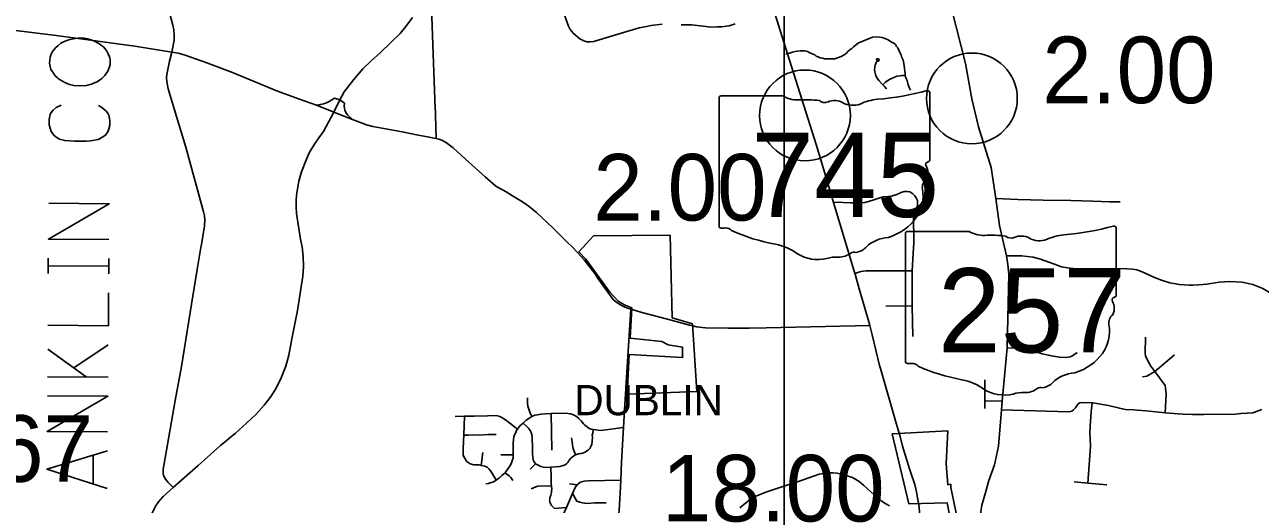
# Model space of a CAD drawing. Extents: x 1659811 to 1934326, y 644115 to 934867.
# Drawn here: x 1781767 to 1802180, y 769000 to 776927 of the extents above; entities that cross this region are included whole.
import ezdxf

# ---------------------------------------------------------------- set-up
doc = ezdxf.new("R2010")
doc.units = 0
for name, color, linetype in [('Default', 7, 'Continuous'), ('GM_X_Adjacent_County_Text', 7, 'Continuous'), ('GM_X_City_Street', 7, 'Continuous'), ('GM_X_Corporation', 7, 'Continuous'), ('GM_X_Corporation_Text', 7, 'Continuous'), ('GM_X_County_Road', 7, 'Continuous'), ('GM_X_State_Route', 7, 'Continuous'), ('GM_X_State_Shield', 7, 'Continuous'), ('SC_Scratch1', 7, 'Continuous')]:
    doc.layers.add(name, color=color, linetype=linetype)

msp = doc.modelspace()

# ---------------------------------------------------------------- linework, layer by layer
at = {"layer": 'Default'}
for centre in [(1797415, 775709), (1794657, 775427)]:
    msp.add_circle(centre, 750, dxfattribs=at)
at = {"layer": 'GM_X_Adjacent_County_Text'}
for p, q in [((1782155, 772817), (1782156, 773069)), ((1783155, 772811), (1783156, 773062)), ((1783155, 772937), (1782156, 772943)), ((1782577, 771255), (1783147, 771637)), ((1782146, 771566), (1782781, 771105)), ((1782143, 771109), (1783143, 771102)), ((1782898, 769805), (1782895, 769340))]:
    msp.add_line(p, q, dxfattribs=at)
for points in [[(1782186, 776234), (1782194, 776210), (1782201, 776187), (1782225, 776147), (1782240, 776124), (1782271, 776084), (1782303, 776052), (1782318, 776036), (1782350, 776013), (1782428, 775973), (1782507, 775941), (1782577, 775924), (1782680, 775916), (1782790, 775923), (1782869, 775946), (1782932, 775969), (1782964, 775985), (1783003, 776008), (1783043, 776039), (1783066, 776063), (1783090, 776086), (1783114, 776118), (1783138, 776157), (1783170, 776228), (1783178, 776267), (1783179, 776346), (1783171, 776377), (1783163, 776409), (1783148, 776448), (1783125, 776488), (1783109, 776511), (1783093, 776535), (1783070, 776559), (1783038, 776583), (1783015, 776599), (1782991, 776614), (1782968, 776630), (1782921, 776654), (1782866, 776678), (1782803, 776694), (1782748, 776703), (1782740, 776703), (1782685, 776703), (1782638, 776704), (1782575, 776696), (1782512, 776681), (1782464, 776665), (1782409, 776642), (1782362, 776619), (1782314, 776580), (1782282, 776548), (1782251, 776517), (1782227, 776486), (1782203, 776439), (1782187, 776392), (1782179, 776344), (1782178, 776289), (1782186, 776234)], [(1782370, 775595), (1782284, 775556), (1782236, 775517), (1782204, 775478), (1782188, 775447), (1782172, 775360), (1782171, 775274), (1782202, 775163), (1782249, 775100), (1782288, 775068), (1782343, 775036), (1782429, 775012), (1782587, 775003), (1782705, 775002), (1782784, 775002), (1782855, 775009), (1782981, 775032), (1783004, 775040), (1783060, 775071), (1783099, 775102), (1783139, 775157), (1783155, 775204), (1783171, 775267), (1783172, 775338), (1783164, 775409), (1783157, 775432), (1783141, 775464), (1783110, 775496), (1783071, 775535), (1783024, 775567), (1782985, 775591)], [(1783158, 773377), (1782158, 773384), (1783162, 773968), (1782163, 773975)], [(1782149, 771959), (1783149, 771952), (1783152, 772496)], [(1783137, 770197), (1782137, 770204), (1783141, 770787), (1782141, 770794)], [(1783131, 769260), (1782133, 769582), (1783135, 769882)]]:
    msp.add_lwpolyline(points, dxfattribs=at)
at = {"layer": 'GM_X_City_Street'}
for points in [[(1784685, 773296), (1784735, 773603), (1784745, 773698), (1784736, 773770), (1784721, 773835), (1784428, 774903), (1784235, 775534), (1784138, 775865), (1784125, 775929), (1784115, 775990), (1784111, 776055), (1784114, 776105), (1784158, 776324), (1784196, 776473), (1784235, 776672), (1784238, 776744), (1784231, 776844), (1784215, 776918), (1784131, 777234), (1783629, 779189), (1783538, 779530), (1783263, 780534), (1783093, 781151)], [(1788551, 775488), (1788549, 775542), (1788539, 775845), (1788512, 776595), (1788492, 777063), (1788470, 777429)], [(1790658, 777159), (1790751, 776900), (1790777, 776845), (1790832, 776780), (1790937, 776695), (1791003, 776661), (1791054, 776642), (1791106, 776642), (1791170, 776649), (1791259, 776676), (1791606, 776781), (1791919, 776873), (1792011, 776891), (1792118, 776916), (1792297, 776934)], [(1786330, 773355), (1786325, 773382), (1786259, 773807), (1786250, 773917), (1786254, 774036), (1786263, 774150), (1786294, 774341), (1786338, 774493), (1786420, 774704), (1786472, 774820), (1786567, 774969), (1786624, 775055), (1786702, 775162), (1786871, 775480), (1786971, 775687), (1787044, 775818), (1787200, 776018), (1787355, 776199), (1787487, 776323), (1787646, 776467), (1787967, 776780), (1788061, 776896), (1788172, 777044)], [(1792613, 776927), (1792783, 776923), (1792974, 776902), (1793100, 776887), (1793202, 776892), (1793276, 776890), (1793407, 776911), (1793502, 776942)], [(1781034, 776910), (1781525, 776843), (1782284, 776747), (1783301, 776608), (1783588, 776571), (1784196, 776473)], [(1794341, 776439), (1794370, 776448), (1794451, 776472), (1794498, 776483), (1794535, 776490), (1794578, 776494), (1794616, 776497), (1794651, 776494), (1794683, 776488), (1794712, 776477), (1794740, 776463), (1794779, 776444), (1794818, 776427), (1794842, 776409), (1794875, 776396), (1794909, 776382), (1794948, 776373), (1794981, 776365), (1795025, 776364), (1795058, 776361), (1795107, 776362), (1795149, 776364), (1795195, 776381), (1795228, 776391), (1795269, 776409), (1795306, 776427), (1795338, 776453), (1795366, 776482), (1795402, 776515), (1795430, 776533), (1795459, 776561), (1795507, 776597), (1795544, 776625), (1795575, 776640), (1795624, 776663), (1795670, 776678), (1795709, 776696), (1795771, 776719), (1795838, 776725), (1795886, 776722), (1795932, 776715), (1795976, 776701), (1796020, 776682), (1796065, 776656), (1796088, 776641), (1796124, 776622), (1796153, 776597), (1796171, 776568), (1796189, 776543), (1796207, 776505), (1796226, 776467), (1796246, 776429), (1796259, 776383), (1796277, 776343), (1796290, 776286), (1796298, 776247), (1796302, 776203), (1796308, 776160), (1796313, 776123), (1796311, 776089), (1796321, 776063), (1796331, 776039), (1796345, 776004), (1796365, 775935), (1796386, 775876), (1796399, 775845)], [(1784196, 776473), (1784304, 776457), (1784415, 776425), (1784775, 776295), (1785202, 776135), (1785945, 775831), (1786304, 775696), (1786590, 775596), (1786871, 775480), (1787181, 775362), (1787342, 775300), (1787411, 775274), (1787519, 775244), (1788001, 775154), (1788269, 775099), (1788392, 775079), (1788532, 775051)], [(1796007, 775869), (1795972, 775907), (1795944, 775934), (1795878, 776005), (1795852, 776042), (1795833, 776072), (1795820, 776102), (1795810, 776150), (1795805, 776187), (1795810, 776221), (1795817, 776259), (1795829, 776286), (1795840, 776313), (1795845, 776321), (1795860, 776324), (1795874, 776331), (1795882, 776338), (1795881, 776352), (1795879, 776360), (1795874, 776365), (1795868, 776368), (1795860, 776365), (1795852, 776365), (1795841, 776361), (1795838, 776356), (1795839, 776349), (1795842, 776339), (1795853, 776323)], [(1795944, 775934), (1795987, 775978), (1796044, 776015), (1796087, 776039), (1796128, 776052), (1796177, 776075), (1796228, 776084), (1796263, 776090), (1796311, 776089)], [(1786971, 775687), (1786883, 775714), (1786799, 775658), (1786752, 775635), (1786705, 775620), (1786653, 775610), (1786590, 775596)], [(1787181, 775362), (1787102, 775437), (1787074, 775478), (1787058, 775514), (1787047, 775581), (1787050, 775630), (1786971, 775687)], [(1788553, 775432), (1788551, 775488)], [(1788566, 775044), (1788553, 775432)], [(1788532, 775051), (1788566, 775044), (1788608, 775035), (1788660, 775017), (1788735, 774973), (1788780, 774943), (1788844, 774889), (1789044, 774708), (1789373, 774412), (1789549, 774260), (1789720, 774163), (1789825, 774100), (1789963, 774014), (1790039, 773965), (1790129, 773902), (1790224, 773825), (1790392, 773663), (1790495, 773565), (1790720, 773346), (1790822, 773244), (1790886, 773175)], [(1795129, 773990), (1795213, 773994), (1795290, 773990), (1795410, 773985), (1795490, 773982), (1795586, 773981), (1795646, 773988), (1795705, 774002), (1795780, 774029), (1795893, 774068), (1795951, 774080), (1796030, 774087), (1796079, 774093), (1796122, 774103), (1796174, 774120), (1796247, 774154), (1796297, 774168), (1796341, 774172), (1796388, 774162), (1796433, 774139), (1796473, 774101), (1796497, 774065), (1796514, 774021), (1796519, 773985), (1796515, 773940), (1796499, 773878), (1796465, 773780), (1796453, 773723), (1796450, 773664), (1796449, 773613), (1796456, 773496), (1796458, 773320), (1796444, 773152)], [(1797809, 774055), (1798172, 774036), (1798594, 774027), (1799049, 774019), (1799413, 774009), (1799687, 773999), (1799865, 774001)], [(1784219, 769275), (1784630, 769643), (1785003, 769974), (1785250, 770175), (1785431, 770342), (1785586, 770486), (1785725, 770636), (1785822, 770764), (1785915, 770909), (1786003, 771088), (1786080, 771284), (1786130, 771467), (1786180, 771733), (1786271, 772205), (1786359, 772769), (1786375, 772928), (1786368, 773096), (1786350, 773256), (1786330, 773355)], [(1784617, 772879), (1784677, 773247), (1784685, 773296)], [(1790886, 773175), (1790898, 773162), (1791008, 773039), (1791186, 772817), (1791243, 772729), (1791399, 772507), (1791490, 772387), (1791532, 772349), (1791580, 772312), (1791646, 772274), (1791724, 772243), (1791780, 772223)], [(1796444, 773152), (1796429, 772857), (1796429, 772273), (1796440, 771773)], [(1797988, 773106), (1798240, 773106), (1798334, 773098), (1798427, 773084), (1798551, 773050), (1798780, 772969), (1798894, 772927), (1798995, 772906), (1799091, 772898), (1799975, 772889), (1800066, 772886), (1800142, 772874), (1800230, 772844), (1800351, 772786), (1800430, 772749), (1800549, 772702), (1800684, 772663), (1800785, 772644), (1800841, 772633), (1801003, 772622), (1801065, 772623)], [(1784213, 769281), (1784139, 769359), (1784090, 769415), (1784062, 769474), (1784054, 769512), (1784054, 769579), (1784065, 769640), (1784254, 770715), (1784357, 771275), (1784523, 772309), (1784617, 772879)], [(1795483, 772817), (1795583, 772849), (1795668, 772859), (1795914, 772857), (1796218, 772860), (1796429, 772857)], [(1801065, 772623), (1801163, 772625), (1801294, 772639), (1801500, 772672), (1801677, 772685), (1801881, 772671), (1802058, 772631), (1802221, 772564), (1802417, 772452), (1802750, 772181), (1802908, 772052), (1802992, 772000), (1803043, 771979), (1803126, 771960), (1803319, 771948)], [(1795994, 772279), (1796429, 772273)], [(1791581, 768845), (1791586, 768900), (1791605, 769182), (1791616, 769401), (1791627, 769698), (1791662, 770268), (1791678, 770556), (1791717, 771182), (1791780, 772223)], [(1792807, 771948), (1792863, 771935), (1792915, 771925), (1793012, 771917), (1793389, 771912), (1793735, 771912), (1794014, 771915), (1795728, 771954)], [(1800611, 770514), (1800625, 770825), (1800614, 770917), (1800606, 770963), (1800436, 771196), (1800371, 771285), (1800320, 771371), (1800283, 771452), (1800276, 771500), (1800285, 771760)], [(1797996, 771587), (1798304, 771573), (1798374, 771568), (1798439, 771537), (1798511, 771510), (1798578, 771485), (1798680, 771462), (1798758, 771449), (1798868, 771430), (1798959, 771427), (1799038, 771436), (1799068, 771447), (1799156, 771510)], [(1800436, 771196), (1800765, 771470)], [(1797627, 770584), (1797628, 770710), (1797629, 771055)], [(1800235, 771108), (1800307, 771117), (1800436, 771196)], [(1790146, 770451), (1790111, 770523), (1790088, 770586), (1790081, 770624), (1790076, 770674), (1790076, 770761)], [(1797628, 770710), (1797918, 770704)], [(1797905, 770559), (1799022, 770530), (1799064, 770538), (1799094, 770562), (1799126, 770593), (1799173, 770659), (1799200, 770678), (1799242, 770682), (1799403, 770676), (1799411, 770676), (1799673, 770632), (1799854, 770588), (1799974, 770563), (1800038, 770564), (1800143, 770554), (1800293, 770542), (1800611, 770514), (1800822, 770496), (1800908, 770489), (1801060, 770485), (1801244, 770484), (1801768, 770492), (1801856, 770499), (1802058, 770514), (1802207, 770567)], [(1799330, 769348), (1799372, 769953), (1799368, 770087), (1799365, 770184), (1799370, 770292), (1799387, 770528), (1799403, 770676)], [(1788880, 770451), (1789030, 770455), (1789035, 770455), (1789192, 770459), (1789410, 770464), (1789554, 770466), (1789598, 770457), (1789628, 770445), (1789679, 770416), (1789734, 770377), (1789910, 770244)], [(1789556, 769401), (1789496, 769501), (1789461, 769552), (1789433, 769586), (1789406, 769611), (1789367, 769632), (1789319, 769640), (1789308, 769642), (1789268, 769650), (1789186, 769654), (1789125, 769668), (1789093, 769692), (1789065, 769714), (1789044, 769749), (1789023, 769786), (1789012, 769816), (1789009, 769856), (1789010, 769914), (1789018, 770043), (1789022, 770141), (1789035, 770455)], [(1789387, 769340), (1789427, 769344), (1789472, 769360), (1789499, 769367), (1789538, 769389), (1789556, 769401), (1789562, 769405), (1789611, 769436), (1789650, 769473), (1789683, 769505), (1789698, 769520), (1789711, 769533), (1789739, 769567), (1789766, 769607), (1789786, 769639), (1789801, 769671), (1789817, 769702), (1789826, 769732), (1789838, 769763), (1789836, 769815), (1789834, 769869), (1789834, 769948), (1789839, 770012), (1789842, 770069), (1789849, 770113), (1789859, 770148), (1789873, 770176), (1789887, 770202), (1789899, 770228), (1789910, 770244), (1789949, 770295), (1790004, 770342), (1790054, 770391), (1790110, 770430), (1790146, 770451), (1790197, 770471), (1790236, 770480), (1790296, 770490), (1790364, 770497), (1790463, 770500), (1790703, 770505), (1790786, 770495), (1790834, 770479), (1790885, 770450), (1790923, 770416), (1790958, 770377), (1790997, 770329), (1791023, 770307), (1791059, 770279), (1791094, 770254), (1791126, 770244), (1791158, 770237), (1791284, 770221), (1791662, 770268)], [(1790477, 769893), (1790463, 770500)], [(1790208, 769671), (1790175, 769720), (1790167, 769742), (1790159, 769780), (1790154, 769833), (1790156, 769916), (1790153, 770120), (1790144, 770147), (1790133, 770188), (1790116, 770222), (1790089, 770259), (1790072, 770275), (1790004, 770342)], [(1790238, 769651), (1790269, 769637), (1790296, 769626), (1790335, 769614), (1790380, 769610), (1790459, 769614), (1790609, 769622), (1790648, 769635), (1790695, 769654), (1790716, 769667), (1790737, 769691), (1790753, 769711), (1790785, 769755), (1790809, 769778), (1790839, 769800), (1790866, 769818), (1790915, 769833), (1790958, 769842), (1790997, 769853), (1791027, 769861), (1791053, 769881), (1791079, 769900), (1791101, 769924), (1791120, 769957), (1791138, 769996), (1791143, 770042), (1791145, 770109), (1791144, 770143), (1791152, 770176), (1791158, 770237)], [(1789022, 770141), (1789097, 770144), (1789163, 770148), (1789279, 770145), (1789417, 770152), (1789557, 770152)], [(1790866, 769818), (1790831, 769903), (1790823, 769936), (1790815, 769984), (1790809, 770033), (1790802, 770099)], [(1789308, 769642), (1789333, 769854)], [(1789631, 769816), (1789836, 769815)], [(1790120, 769582), (1790208, 769671), (1790237, 769652), (1790238, 769651)], [(1790715, 768948), (1790521, 768932), (1790491, 768958), (1790470, 768979), (1790460, 769000), (1790446, 769026), (1790443, 769042), (1790439, 769063), (1790440, 769087), (1790443, 769109), (1790460, 769152), (1790470, 769195), (1790472, 769219), (1790478, 769255), (1790470, 769292), (1790469, 769305), (1790467, 769331), (1790465, 769451), (1790459, 769614)], [(1789698, 769520), (1789768, 769470), (1789798, 769442), (1789832, 769393)], [(1790553, 768589), (1790715, 768948), (1790816, 769180), (1790859, 769277), (1790893, 769321), (1790940, 769358), (1790968, 769370), (1791009, 769383), (1791080, 769388), (1791616, 769401)], [(1793579, 768939), (1793674, 769021), (1793754, 769080), (1793843, 769132), (1794027, 769208), (1794341, 769310), (1794532, 769373), (1794798, 769467), (1794892, 769496), (1795005, 769514), (1795068, 769519), (1795116, 769518), (1795189, 769512), (1795261, 769500), (1795334, 769477), (1795440, 769440), (1795497, 769407), (1795552, 769375), (1795628, 769311), (1795747, 769206), (1795844, 769120), (1795901, 769069), (1795996, 769010), (1796054, 768976)], [(1799105, 769369), (1799330, 769348), (1799645, 769319)], [(1783804, 768056), (1783780, 768394), (1783780, 768450), (1783783, 768525), (1783798, 768648), (1783813, 768714), (1783836, 768775), (1783866, 768846), (1783898, 768910), (1783928, 768970), (1783978, 769042), (1784055, 769126), (1784219, 769275), (1784213, 769281)], [(1790135, 769254), (1790209, 769289), (1790243, 769301), (1790469, 769305)], [(1790767, 769338), (1790893, 769321)], [(1790816, 769180), (1790890, 769050), (1790937, 769034), (1790980, 769025), (1791018, 769016), (1791067, 769014), (1791178, 769023), (1791375, 769026)]]:
    msp.add_lwpolyline(points, dxfattribs=at)
at = {"layer": 'GM_X_Corporation'}
msp.add_lwpolyline([(1791769, 771744), (1792292, 771693), (1792400, 771637), (1792636, 771596), (1792636, 771425), (1791754, 771473), (1791720, 770818), (1792869, 770863), (1792799, 771981), (1792464, 772084), (1792432, 773446), (1791163, 773438), (1790923, 773175), (1791037, 773050), (1791431, 772506), (1791571, 772357), (1791625, 772322), (1791688, 772291), (1791795, 772249)], close=True, dxfattribs=at)
msp.add_lwpolyline([(1791769, 771744), (1792292, 771693), (1792400, 771637), (1792636, 771596), (1792636, 771425), (1791754, 771473), (1791720, 770818), (1792869, 770863), (1792799, 771981), (1792464, 772084), (1792432, 773446), (1791163, 773438), (1790923, 773175), (1791037, 773050), (1791431, 772506), (1791571, 772357), (1791625, 772322), (1791688, 772291), (1791795, 772249)], close=True, dxfattribs=at)
msp.add_lwpolyline([(1797178, 768750), (1797069, 769278), (1797065, 769330), (1797015, 769322), (1796989, 769674), (1797017, 770212), (1796099, 770163), (1796374, 769005), (1797006, 769026), (1797045, 768825)], dxfattribs=at)
msp.add_lwpolyline([(1797178, 768750), (1797069, 769278), (1797065, 769330), (1797015, 769322), (1796989, 769674), (1797017, 770212), (1796099, 770163), (1796374, 769005), (1797006, 769026), (1797045, 768825)], dxfattribs=at)
at = {"layer": 'GM_X_County_Road'}
msp.add_lwpolyline([(1791780, 772223), (1791982, 772166), (1792387, 772058), (1792748, 771962), (1792807, 771948)], dxfattribs=at)
at = {"layer": 'GM_X_State_Route'}
for points in [[(1794934, 774636), (1794841, 774945), (1794370, 776448), (1793373, 779630)], [(1797529, 768657), (1797548, 768766), (1797581, 768985), (1797643, 769214), (1797690, 769377), (1797786, 769653), (1797853, 769962), (1797905, 770559), (1797918, 770704), (1797996, 771587), (1797996, 771591), (1798023, 772805), (1798010, 772961), (1797988, 773106), (1797874, 773609), (1797809, 774055), (1797734, 774564), (1797526, 775241), (1797415, 775699), (1797309, 776284), (1797086, 777175)], [(1795323, 773347), (1795129, 773990), (1794934, 774636)], [(1795488, 772801), (1795483, 772817), (1795323, 773347)], [(1795700, 772053), (1795555, 772562), (1795488, 772801)], [(1795765, 771801), (1795728, 771954), (1795700, 772053)], [(1795905, 771243), (1795890, 771296), (1795765, 771801)], [(1796165, 770339), (1795905, 771243)], [(1796384, 769586), (1796267, 769959), (1796228, 770123), (1796165, 770339)], [(1796513, 769134), (1796505, 769178), (1796470, 769325), (1796410, 769506), (1796384, 769586)], [(1796522, 769083), (1796519, 769102), (1796513, 769134)], [(1796549, 768771), (1796548, 768877), (1796544, 768948), (1796522, 769083)]]:
    msp.add_lwpolyline(points, dxfattribs=at)
at = {"layer": 'GM_X_State_Shield'}
for p, q in [((1793238, 775714), (1793238, 773601)), ((1794292, 775750), (1793273, 775750)), ((1796719, 774697), (1796719, 775803)), ((1796718, 774698), (1796719, 774697)), ((1796318, 773474), (1796318, 771361)), ((1797372, 773511), (1796353, 773511)), ((1799799, 772458), (1799799, 773563)), ((1799798, 772458), (1799799, 772458))]:
    msp.add_line(p, q, dxfattribs=at)
for centre, major_axis, start_param, end_param in [((1793278, 775719), (40.3, 0), 1.712693, 3.28349), ((1794535, 775996), (391, 0), 4.042523, 4.731795), ((1795479, 778632), (3691, 0), 4.814394, 5.042369), ((1796680, 775807), (38.7, 0), 6.141152, 7.989035), ((1794664, 774564), (1404, 0), 1.404758, 1.657858), ((1794983, 775730), (113, 0), 3.836095, 5.185415), ((1795149, 775485), (235, 0), 0.950623, 2.079405), ((1795451, 775820), (282, 0), 4.081561, 5.145723), ((1795950, 775105), (743, 0), 1.699011, 2.107814), ((1796677, 774693), (41.5, 0), 5.05454, 6.418171), ((1796710, 774616), (60, 0), 1.883978, 3.671073), ((1796328, 774476), (360, 0), 5.934695, 6.695948), ((1796858, 774235), (262, 0), 2.387724, 3.262537), ((1795686, 774094), (923, 0), 5.101752, 6.440018), ((1793279, 773596), (40.7, 0), 3.00124, 4.508301), ((1793285, 773812), (310, 0), 4.665946, 4.897461), ((1793348, 773479), (112, 0), 0.519207, 1.627899), ((1794761, 775378), (2665, 0), 4.195997, 4.488961), ((1796358, 773479), (40.3, 0), 1.712693, 3.28349), ((1797615, 773756), (391, 0), 4.042523, 4.731795), ((1797744, 772324), (1404, 0), 1.404758, 1.657858), ((1799030, 772865), (743, 0), 1.699011, 2.107814), ((1798559, 776392), (3691, 0), 4.814394, 5.042369), ((1799760, 773568), (38.7, 0), 6.141152, 7.989035), ((1793967, 772651), (834, 0), 0.823519, 1.323587), ((1795434, 773396), (298, 0), 4.937069, 5.64225), ((1796075, 773007), (506, 0), 1.647645, 2.488434), ((1798063, 773490), (113, 0), 3.836095, 5.185415), ((1798229, 773246), (235, 0), 0.950623, 2.079405), ((1798531, 773581), (282, 0), 4.081561, 5.145723), ((1794869, 773468), (529, 0), 4.026481, 4.996735), ((1795175, 772738), (435, 0), 1.495662, 1.94098), ((1795213, 773310), (282, 0), 4.691044, 5.507374), ((1795468, 773105), (79.4, 0), 1.147584, 2.315152), ((1799757, 772453), (41.5, 0), 5.05454, 6.418171), ((1799790, 772377), (60, 0), 1.883978, 3.671073), ((1799408, 772237), (360, 0), 5.934695, 6.695948), ((1799938, 771995), (262, 0), 2.387724, 3.262537), ((1798766, 771854), (923, 0), 5.101752, 6.440018), ((1796359, 771357), (40.7, 0), 3.00124, 4.508301), ((1796365, 771573), (310, 0), 4.665946, 4.897461), ((1796428, 771239), (112, 0), 0.519207, 1.627899), ((1797841, 773138), (2665, 0), 4.195997, 4.488961), ((1797047, 770412), (834, 0), 0.823519, 1.323587), ((1798514, 771156), (298, 0), 4.937069, 5.64225), ((1799155, 770768), (506, 0), 1.647645, 2.488434), ((1797949, 771229), (529, 0), 4.026481, 4.996735), ((1798255, 770498), (435, 0), 1.495662, 1.94098), ((1798293, 771071), (282, 0), 4.691044, 5.507374), ((1798548, 770866), (79.4, 0), 1.147584, 2.315152)]:
    msp.add_ellipse(centre, major_axis=major_axis, ratio=0.8, start_param=start_param, end_param=end_param, dxfattribs=at)
at = {"layer": 'SC_Scratch1'}
msp.add_lwpolyline([(1659811, 738617), (1659811, 934867), (1794311, 934867), (1794311, 738617)], close=True, dxfattribs=at)

# ---------------------------------------------------------------- texts
at = {"layer": 'Default'}
for s, p in [('2.00', (1798579, 775630)), ('2.00', (1791161, 773690)), ('13.67', (1779215, 769372)), ('18.00', (1792293, 768716))]:
    msp.add_text(s, height=1100, dxfattribs=at).set_placement(p)
at = {"layer": 'GM_X_Corporation_Text'}
msp.add_text('DUBLIN', height=500, rotation=0, dxfattribs=at).set_placement((1790848, 770472))
at = {"layer": 'GM_X_State_Shield'}
for s, p in [('745', (1793770, 773750)), ('257', (1796854, 771510))]:
    msp.add_text(s, height=1392.2, dxfattribs=at).set_placement(p)

doc.saveas('drawing.dxf')
